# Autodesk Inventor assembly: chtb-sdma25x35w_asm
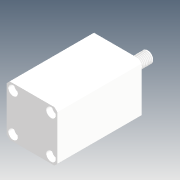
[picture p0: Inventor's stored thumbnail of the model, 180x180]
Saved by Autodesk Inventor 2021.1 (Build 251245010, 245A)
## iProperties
Company: Microsoft
Created: 2018-05
Part Number: chtb-sdma25x35w_asm
Description: STEP AP214
Document SubType Name: Assembly
Designer: user
Title: chtb-sdma25x35w_asm.STEP
Author: Windows
Revision Number: ÈÎºÎ
Sending System: SolidWorks 2015
Preprocessor: SwSTEP 2.0
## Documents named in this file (4)
- D:\Vault_2016\Projekty\Clamptek\Hydraulic\CHTB\CHTB-25\Inventor\chtb-sdma25x35w\chtb-sdma25x35w_asm.iam
- D:\Vault_2016\Projekty\Clamptek\Hydraulic\CHTB\CHTB-25\Inventor\chtb-sdma25x35w\CHTB-25QG.ipt
- D:\Vault_2016\Projekty\Clamptek\Hydraulic\CHTB\CHTB-25\Inventor\chtb-sdma25x35w\CHTB-SDMA25X35NBT.ipt
- D:\Vault_2016\Projekty\Clamptek\Hydraulic\CHTB\CHTB-25\Inventor\chtb-sdma25x35w\CHTB-SDMA25X35WHSG.ipt
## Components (3 placed, 3 different names)
1. CHTB-25QG_1
2. CHTB-SDMA25X35NBT_2
3. CHTB-SDMA25X35WHSG_3
